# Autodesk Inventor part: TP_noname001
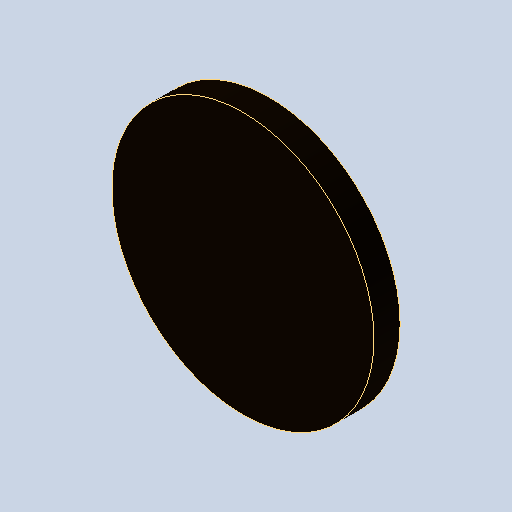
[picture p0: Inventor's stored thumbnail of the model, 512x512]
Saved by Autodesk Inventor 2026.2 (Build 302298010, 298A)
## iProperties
Created: 2026-10
Part Number: TP_noname001
Material: Générique
Document SubType Name: Modeling
Designer: mel
Density: 1 g/cm^3
Appearance: Par défaut
Author: mel
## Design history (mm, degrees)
feature "Base1"
node "Solide1"
